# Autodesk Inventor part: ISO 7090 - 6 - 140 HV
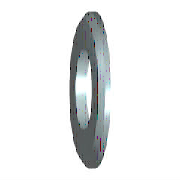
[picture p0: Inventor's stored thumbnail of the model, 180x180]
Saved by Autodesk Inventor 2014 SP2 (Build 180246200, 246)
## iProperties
Created: 2013-02
Part Number: ISO 7090 - 6 - 140 HV
Material: Stainless Steel
Description: Plain washers, charmfered - Normal series - Product grade A
Document SubType Name: Modeling
Standard: ISO 7090
Designer: SFC
Standard Revision: Second edition 2000-06-01
Standards Organization: ISO
Language: en-US
Size Designation: 6 - 140 HV
Categories: <MemberInstance><Categories><Category DisplayName="Fasteners" InternalName="e4da775c-781d-43d5-af7c-5136215cf5a6" Mnemonic="FSTN"><Category DisplayName="Washers
Density: 8.08 g/cm^3
Appearance: Semi-Polished
IsCustomPart: 0
Author: SFC
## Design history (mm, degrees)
body "Solid1"
sketch "Sketch"
  geometry: C1 r 6 at (0, 0); C2 r 3.2 at (0, 0); 1 further point
  constraints: 2 centre point, 2 coincident
  dimensions: "d0" = 6.4 diameter of C2 (= SD1); "d1" = 12 diameter of C1 (= SD2)
extrude "Body" new body sketch "Sketch" distance "d2" = 1.6 (= SD); taper "d3" = 0 deg
workaxis "Work Axis1"
workplane "Work Plane1"
chamfer "Chamfer" distance "d4" = 0.8 (= PHH); stored, may be unused: angle "d5" = 45 deg, second distance "d8" = 0.8 (= PHH)
other parameters: "SD1" = 6.4 [user parameter; used in 1 equation term], "SD2" = 12 [user parameter; used in 1 equation term], "SD" = 1.6 [user parameter; used in 1 equation term], "PHH" = 0.8 [user parameter; used in 2 equation terms], "FAWI" = 45 deg [user parameter], "d6" = 0, "d7" = 0, "d9" = 0, "d10" = 0, "NND" = 6 [user parameter]
